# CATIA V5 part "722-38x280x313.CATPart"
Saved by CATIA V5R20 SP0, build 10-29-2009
Part number: 722-38x280x313
Definition: NONE
Nomenclature: 722-38x280x313
Source: Unknown
Description: 722-38x280x313
Bounding box of the stored display mesh (mm): x -19 to 19, y -18.807 to 18.807, z -265 to 48
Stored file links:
  C:\Users\Utente\Desktop\IO LAVORO\3D X SITO CF\X SITO\722\722-38x280x313.CATPart

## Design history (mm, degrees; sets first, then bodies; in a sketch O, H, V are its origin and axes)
Body1 "722-38x280x313" (main body)
  Solid1: solid without history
